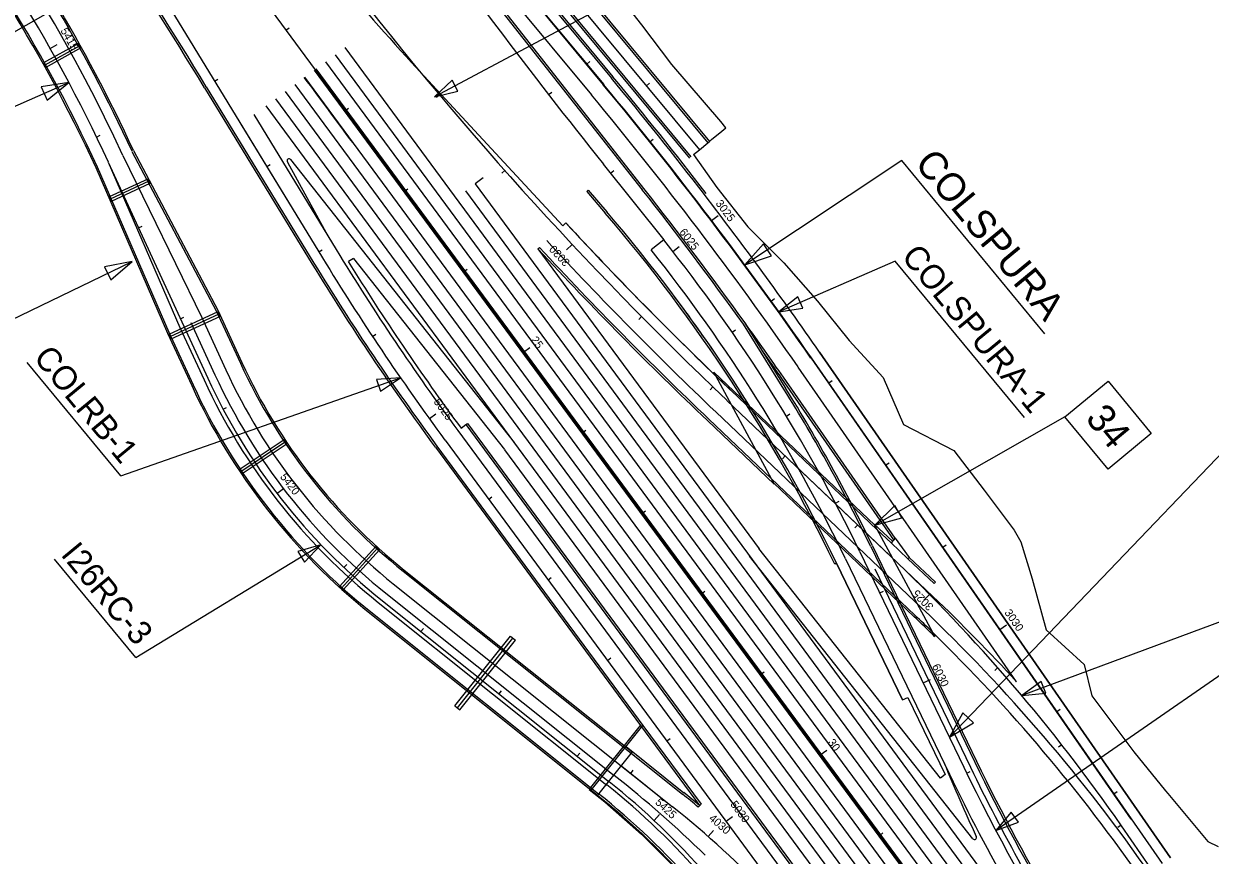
# Model space of a CAD drawing. Extents: x 1944333 to 1975203, y 788957 to 827579.
# Drawn here: x 1970195 to 1971381, y 796150 to 796981 of the extents above; entities that cross this region are included whole.
import ezdxf

# ---------------------------------------------------------------- set-up
doc = ezdxf.new("R2010")
doc.units = 0
for name, color, linetype in [('BR_CENTER LINES', 7, 'Continuous'), ('BR_CONCRETE', 7, 'Continuous'), ('RD_HC_CL_Rel', 7, 'Continuous'), ('RD_HC_Data_Tic_Rel', 7, 'Continuous'), ('RD_HC_TX_Rel_Sta50', 7, 'Continuous'), ('RD_PD_ALT1_LnLine', 7, 'Continuous'), ('RD_PD_ALT1_TrvlWay', 7, 'Continuous'), ('RD_PD_ALT3_LnLine', 7, 'Continuous'), ('RD_PD_CstnLmt', 7, 'Continuous'), ('RD_PD_GR', 7, 'Continuous'), ('RD_PD_MedBWall', 7, 'Continuous'), ('RD_PD_PaveShd', 7, 'Continuous'), ('RD_PD_WallFill', 7, 'Continuous'), ('RD_QTY_Conc4Structures', 7, 'Continuous'), ('RD_TX_RoadID', 7, 'Continuous')]:
    doc.layers.add(name, color=color, linetype=linetype)

msp = doc.modelspace()

# ---------------------------------------------------------------- linework, layer by layer
at = {"layer": 'BR_CENTER LINES'}
for p, q in [((1970250.9, 796958.7), (1970215.9, 796939.3)), ((1970320, 796823.3), (1970281.3, 796805.5)), ((1970390.1, 796690.4), (1970341, 796667.8)), ((1970456.7, 796562.8), (1970411.8, 796532.8)), ((1970548.6, 796456.5), (1970512.4, 796416.4)), ((1970628.3, 796297.1), (1970683.8, 796366.6))]:
    msp.add_line(p, q, dxfattribs=at)
at = {"layer": 'BR_CONCRETE'}
for p, q in [((1970249.7, 796960.9), (1970214.7, 796941.5)), ((1970252.1, 796956.5), (1970217.1, 796937.1)), ((1970252.1, 796956.5), (1970249.7, 796960.9)), ((1970214.7, 796941.5), (1970217.1, 796937.1)), ((1970303.1, 796853.2), (1970387.4, 796693.9)), ((1970304.6, 796854), (1970388.9, 796694.6)), ((1970267, 796837), (1970338.6, 796671.6)), ((1970268.5, 796837.6), (1970340.1, 796672.3)), ((1970318.9, 796825.5), (1970280.2, 796807.7)), ((1970321, 796821), (1970318.9, 796825.5)), ((1970321, 796821), (1970282.3, 796803.2)), ((1970280.2, 796807.7), (1970282.3, 796803.2)), ((1970387.4, 796693.9), (1970411.5, 796641.4)), ((1970388.9, 796694.6), (1970413, 796642.1)), ((1970389.1, 796692.7), (1970340, 796670.1)), ((1970391.2, 796688.1), (1970342.1, 796665.6)), ((1970391.2, 796688.1), (1970389.1, 796692.7)), ((1970338.6, 796671.6), (1970362.8, 796619)), ((1970340, 796670.1), (1970342.1, 796665.6)), ((1970340.1, 796672.3), (1970364.3, 796619.7)), ((1970944.4, 796521.6), (1970884.6, 796632.6)), ((1971045.5, 796479.6), (1970884.6, 796632.6)), ((1971047.9, 796475), (1970887.1, 796628)), ((1970455.3, 796564.9), (1970410.4, 796534.9)), ((1970458.1, 796560.7), (1970455.3, 796564.9)), ((1970458.1, 796560.7), (1970413.2, 796530.7)), ((1970410.4, 796534.9), (1970413.2, 796530.7)), ((1971085.6, 796389.5), (1970941.9, 796526.2)), ((1971084.5, 796388.3), (1970944.4, 796521.6)), ((1971105.6, 796367.9), (1971045.5, 796479.6)), ((1970546.7, 796458.2), (1970510.6, 796418.1)), ((1970550.5, 796454.9), (1970546.7, 796458.2)), ((1970550.5, 796454.9), (1970514.3, 796414.8)), ((1970574.3, 796433.4), (1970801.9, 796251.7)), ((1970575.3, 796434.7), (1970802.9, 796252.9)), ((1970510.6, 796418.1), (1970514.3, 796414.8)), ((1970540.8, 796391.5), (1970768.4, 796209.8)), ((1970541.8, 796392.8), (1970769.4, 796211)), ((1970625.7, 796299.1), (1970681.3, 796368.7)), ((1970630.8, 796295.1), (1970686.3, 796364.6)), ((1970681.3, 796368.7), (1970686.3, 796364.6)), ((1970625.7, 796299.1), (1970630.8, 796295.1)), ((1970802.9, 796252.9), (1970768.4, 796209.8))]:
    msp.add_line(p, q, dxfattribs=at)
for centre, radius, start, end in [((1968885.8, 796201.6), 1520.4, 24.6902, 54.7761), ((1968885.8, 796201.6), 1522, 24.6902, 54.7761), ((1968885.8, 796201.6), 1560, 24.6902, 49.7691), ((1968885.8, 796201.6), 1561.6, 24.6902, 49.7691), ((1970931.2, 796880.4), 572, 204.6902, 231.3903), ((1970931.2, 796880.4), 570.4, 204.6902, 231.3903), ((1970931.2, 796880.4), 625.6, 204.6902, 231.3903), ((1970931.2, 796880.4), 624, 204.6902, 231.3903), ((1969897.2, 795140.5), 1722.4, 45.4469, 46.4244), ((1969897.2, 795140.5), 1724, 45.6209, 46.4244)]:
    msp.add_arc(centre, radius, start, end, dxfattribs=at)
at = {"layer": 'RD_HC_CL_Rel'}
for p, q in [((1970371.4, 797456.1), (1970870.2, 796854.8)), ((1970391.3, 797381.2), (1970774.1, 796919.7)), ((1970235.6, 797274.6), (1971221.4, 795937.4)), ((1970226.8, 797183.8), (1970493.6, 796746.7)), ((1970279.5, 796842.4), (1970378.8, 796626.4)), ((1970774.1, 796840.5), (1970834.5, 796764.7)), ((1970981.7, 796646.5), (1971301.4, 796185.7)), ((1971060.5, 796449.2), (1970897.5, 796604.3)), ((1970616, 796564.6), (1971026.4, 796007.8)), ((1971030.6, 796452.9), (1971134.5, 796237.5)), ((1970551.8, 796405.3), (1970780.1, 796223)), ((1970792.6, 796238.6), (1970843.3, 796198.1)), ((1971378.8, 796053.9), (1971291.9, 796179.1))]:
    msp.add_line(p, q, dxfattribs=at)
for centre, radius, start, end in [((1969482, 796626.9), 1166, 35.6021, 163.611), ((1968885.8, 796201.6), 1534, 24.6902, 54.7761), ((1976020.6, 801023.6), 6710, 215.60211, 218.56681), ((1973505.9, 799345.7), 3784, 217.5434, 226.4244), ((1967695.8, 794366.3), 3999.5, 34.7587, 39.6755), ((1969544.4, 795736), 1650, 25.75, 38.5668), ((1972641.1, 798057.5), 2516, 211.3977, 216.3977), ((1970931.2, 796880.4), 608, 204.6902, 231.3903), ((1969854.2, 795181.4), 1750, 34.7587, 46.4244), ((1972899.9, 797089), 1960, 205.75, 218.6115), ((1970309.6, 795633.8), 754, 30.7638, 51.3903), ((1970211.8, 795407.3), 1012, 36.3977, 51.3903)]:
    msp.add_arc(centre, radius, start, end, dxfattribs=at)
at = {"layer": 'RD_HC_Data_Tic_Rel'}
for p, q in [((1970456.9, 796974.4), (1970460.1, 796976.8)), ((1970221.4, 796956.1), (1970228.4, 796960)), ((1970757.7, 796940.3), (1970760.7, 796942.9)), ((1970385.7, 796923.4), (1970389.1, 796925.5)), ((1970817.2, 796918.7), (1970820.3, 796921.2)), ((1970610.3, 796909.6), (1970607.3, 796907)), ((1970719.5, 796910), (1970722.6, 796912.4)), ((1970516.2, 796894), (1970519.5, 796896.3)), ((1970267.7, 796867.5), (1970271.3, 796869.2)), ((1970821, 796862.9), (1970824.1, 796865.4)), ((1970437.8, 796838), (1970441.2, 796840.1)), ((1970675.7, 796834), (1970672.7, 796831.3)), ((1970781.3, 796831.4), (1970784.5, 796833.9)), ((1970575.6, 796813.5), (1970578.8, 796815.8)), ((1970882.4, 796784), (1970888.8, 796788.9)), ((1970309.7, 796776.7), (1970313.3, 796778.4)), ((1970489.9, 796752.7), (1970493.3, 796754.8)), ((1970743.1, 796760.1), (1970737.2, 796754.6)), ((1970843.6, 796753.2), (1970849.9, 796758.1)), ((1970634.9, 796733), (1970638.1, 796735.3)), ((1970941.9, 796703.6), (1970945.1, 796706)), ((1970351.5, 796685.9), (1970355.1, 796687.5)), ((1970812.4, 796688), (1970809.5, 796685.1)), ((1970543.5, 796668.2), (1970546.8, 796670.5)), ((1970902.9, 796672.6), (1970906.2, 796674.9)), ((1970694.3, 796652.5), (1970700.7, 796657.2)), ((1970999.4, 796621.8), (1971002.7, 796624.1)), ((1970883.5, 796617.7), (1970880.8, 796614.8)), ((1970394.1, 796595.4), (1970397.7, 796597.3)), ((1970600.3, 796586), (1970606.8, 796590.7)), ((1970957.1, 796588.6), (1970960.5, 796590.7)), ((1970753.6, 796572), (1970756.8, 796574.4)), ((1970955.9, 796548.7), (1970953.2, 796545.8)), ((1971056.4, 796539.7), (1971059.7, 796541.9)), ((1970448, 796511.3), (1970454.4, 796516.2)), ((1970659.6, 796505.4), (1970662.8, 796507.8)), ((1971006.1, 796501.5), (1971009.7, 796503.4)), ((1970812.9, 796491.5), (1970816.2, 796493.9)), ((1971028.4, 796479.8), (1971025.6, 796476.9)), ((1971113.4, 796457.5), (1971116.7, 796459.8)), ((1970515, 796437.2), (1970517.7, 796440.1)), ((1970718.9, 796424.9), (1970722.1, 796427.3)), ((1970872.3, 796411), (1970875.5, 796413.4)), ((1971050.4, 796411.8), (1971054, 796413.6)), ((1971100.2, 796410.2), (1971094.5, 796404.6)), ((1970591.9, 796373.3), (1970594.4, 796376.4)), ((1971170.4, 796375.3), (1971177, 796379.9)), ((1970778.2, 796344.4), (1970781.5, 796346.8)), ((1970931.6, 796330.5), (1970934.8, 796332.9)), ((1971168.4, 796337.1), (1971165.4, 796334.4)), ((1970670, 796310.9), (1970672.5, 796314)), ((1971093.8, 796321.8), (1971101, 796325.2)), ((1971227.4, 796293.2), (1971230.7, 796295.5)), ((1970837.6, 796263.9), (1970840.8, 796266.3)), ((1970991, 796250), (1970997.4, 796254.8)), ((1971232.2, 796260.1), (1971229.1, 796257.7)), ((1970748.1, 796248.5), (1970750.6, 796251.6)), ((1970801.6, 796231.4), (1970804.1, 796234.5)), ((1971137.3, 796231.7), (1971140.9, 796233.4)), ((1971284.4, 796211), (1971287.7, 796213.3)), ((1970824.8, 796184.3), (1970830.3, 796190.2)), ((1970896.9, 796183.5), (1970903.4, 796188.2)), ((1970879, 796168.2), (1970884.3, 796174.2)), ((1971050.3, 796169.5), (1971053.5, 796171.9)), ((1971291.6, 796179.7), (1971288.3, 796177.4))]:
    msp.add_line(p, q, dxfattribs=at)
at = {"layer": 'RD_PD_ALT1_LnLine'}
for p, q in [((1970515.8, 796956.9), (1971235.5, 795980.7)), ((1970506.2, 796949.8), (1971226.1, 795973.2)), ((1970465.9, 796920.1), (1971186.9, 795942.1)), ((1970456.3, 796913), (1971177.5, 795934.6)), ((1970446.6, 796905.8), (1971168.1, 795927.1)), ((1970636.3, 796813.6), (1971204.2, 796043.4)), ((1970362, 796682.2), (1970386.1, 796629.7)), ((1970556.8, 796411.5), (1970785.1, 796229.2))]:
    msp.add_line(p, q, dxfattribs=at)
for centre, radius, start, end in [((1970931.2, 796880.4), 600, 204.6902, 231.3903), ((1970125.7, 795385.7), 1070.7, 45.5181, 51.9846)]:
    msp.add_arc(centre, radius, start, end, dxfattribs=at)
at = {"layer": 'RD_PD_ALT1_TrvlWay'}
for p, q in [((1970379.9, 797463.1), (1970878.6, 796861.8)), ((1970363, 797449.1), (1970861.7, 796847.8)), ((1970616.6, 797110.3), (1970774.5, 796920)), ((1970604.3, 797100.1), (1970762.2, 796909.8)), ((1970496.5, 796942.6), (1971216.7, 795965.8)), ((1970475.6, 796927.2), (1971196.3, 795949.6)), ((1970436.9, 796898.7), (1971158.7, 795919.6)), ((1970424.9, 796889.9), (1970507.2, 796755.1)), ((1970412, 796880.3), (1970493.6, 796746.7)), ((1970294.1, 796849.1), (1970372.9, 796687.2)), ((1970279.5, 796842.4), (1970351.1, 796677.2)), ((1970458.5, 796842.5), (1970497.1, 796771.6)), ((1970461.7, 796844.9), (1970685, 796562.2)), ((1970646, 796820.8), (1971250.6, 796000.6)), ((1970834.5, 796764.7), (1970822, 796754.7)), ((1970372.9, 796687.2), (1970397, 796634.7)), ((1970351.1, 796677.2), (1970375.2, 796624.7)), ((1971332.8, 796141.4), (1970982.1, 796646.7)), ((1971187.2, 796323.1), (1970968.9, 796637.6)), ((1971103.5, 796408.3), (1970897.5, 796604.3)), ((1970886.5, 796592.7), (1971092.5, 796396.7)), ((1970616, 796564.6), (1971026.4, 796007.8)), ((1970628.8, 796574), (1971128.6, 795896.1)), ((1971143.5, 796166.1), (1970920.3, 796448.7)), ((1971016.2, 796445.9), (1971120.1, 796230.5)), ((1970564.3, 796420.9), (1970843.3, 796198.1)), ((1970549.3, 796402.1), (1970777.6, 796219.8))]:
    msp.add_line(p, q, dxfattribs=at)
for centre, radius, start, end in [((1968885.8, 796201.6), 1534, 24.6902, 54.7761), ((1968885.8, 796201.6), 1550, 24.6902, 49.7691), ((1967695.8, 794366.3), 4000, 34.7587, 39.6755), ((1967695.8, 794366.3), 3984, 34.7587, 39.6755), ((1970460.1, 796843.7), 2, 36.3977, 216.3977), ((1972641.1, 798057.5), 2500, 211.3977, 216.3977), ((1973505.9, 799345.7), 3800, 222.7981, 226.4244), ((1969544.4, 795736), 1634, 25.75, 38.5668), ((1972641.1, 798057.5), 2516, 211.3977, 216.3977), ((1970931.2, 796880.4), 588, 204.6902, 231.3903), ((1970931.2, 796880.4), 612, 204.6902, 231.3903), ((1969897.2, 795140.5), 1734, 34.7587, 46.4244), ((1969897.2, 795140.5), 1750, 42.5124, 46.4244), ((1972945.2, 796997.9), 1980.5, 202.444, 204.759), ((1970309.6, 795633.8), 750, 30.7638, 51.3903), ((1972899.9, 797089), 1976, 205.75, 213.4208), ((1970211.8, 795407.3), 1012, 36.3977, 51.3903), ((1971145.1, 796167.3), 2, 216.3977, 36.3977)]:
    msp.add_arc(centre, radius, start, end, dxfattribs=at)
at = {"layer": 'RD_PD_ALT3_LnLine'}
msp.add_arc((1961247.8, 790023.8), 11524, 36.39766, 36.80076, dxfattribs=at)
at = {"layer": 'RD_PD_CstnLmt'}
for p, q in [((1971338.2, 796211.2), (1971378.2, 796163.3)), ((1971378.2, 796163.3), (1971388.6, 796158.4))]:
    msp.add_line(p, q, dxfattribs=at)
for points in [[(1970864.4, 796850), (1970870.2, 796854.8), (1970878.6, 796861.8), (1970880.2, 796863.1), (1970882.3, 796864.9), (1970892.5, 796873.3), (1970896.6, 796876.7), (1970891.7, 796883.1), (1970875.4, 796902), (1970842.7, 796939.9), (1970812.6, 796979.8), (1970781.8, 797019.3)], [(1970864.4, 796850), (1970887.5, 796817.2), (1970918.6, 796777.7), (1970954.7, 796741.7), (1970988.1, 796703.5), (1971019.7, 796664.1), (1971053.9, 796627), (1971074.1, 796580.2), (1971124.4, 796554.2), (1971154.7, 796514.4), (1971184.8, 796474.4), (1971191.5, 796463), (1971202.8, 796426), (1971216.6, 796374.8), (1971254.6, 796340.3), (1971262.4, 796308.9), (1971274.2, 796293.1), (1971304.3, 796253), (1971335.9, 796214.1), (1971338.2, 796211.2)], [(1970760, 796215.3), (1970775.5, 796202.9), (1970812.2, 796170.8), (1970812.2, 796170.8), (1970812.3, 796170.7), (1970846.6, 796136.3)]]:
    msp.add_lwpolyline(points, dxfattribs=at)
at = {"layer": 'RD_PD_GR'}
for p, q in [((1970990.3, 796652.4), (1971340.9, 796147.1)), ((1971079.9, 796447.3), (1971078.6, 796445.9)), ((1971104.7, 796421.1), (1971078.6, 796445.9)), ((1971106, 796422.5), (1971079.9, 796447.3)), ((1971073.2, 796304.8), (1971007.2, 796441.6)), ((1971106, 796422.5), (1971104.7, 796421.1))]:
    msp.add_line(p, q, dxfattribs=at)
for centre, radius, start, end in [((1967695.8, 794366.3), 4010, 34.7587, 37.546), ((1973505.9, 799345.7), 3774, 222.7981, 226.0583), ((1969897.2, 795140.5), 1724, 34.7587, 45.6209)]:
    msp.add_arc(centre, radius, start, end, dxfattribs=at)
at = {"layer": 'RD_PD_MedBWall'}
for p, q in [((1970485.2, 796934.3), (1971205.4, 795957.4)), ((1970486.9, 796935.5), (1971207, 795958.7)), ((1971064.4, 796464.9), (1970952.5, 796626.2)), ((1971065.9, 796466.4), (1970954.1, 796627.4)), ((1970811.2, 796279.4), (1970870.3, 796199.3)), ((1970813.8, 796279.4), (1970871.9, 796200.5)), ((1970780.8, 796268.5), (1970853.3, 796210.6)), ((1970796.9, 796258.2), (1970854.6, 796212.1)), ((1970871.9, 796200.5), (1970869, 796197.8))]:
    msp.add_line(p, q, dxfattribs=at)
for centre, radius, start, end in [((1967695.8, 794366.3), 3966, 34.7587, 35.7176), ((1967695.8, 794366.3), 3964, 34.7587, 35.2497), ((1970211.8, 795407.3), 1028, 50.2601, 51.3903), ((1970211.8, 795407.3), 1030, 50.2601, 51.3903)]:
    msp.add_arc(centre, radius, start, end, dxfattribs=at)
at = {"layer": 'RD_PD_PaveShd'}
for p, q in [((1970381.4, 797464.4), (1970880.2, 796863.1)), ((1970361.4, 797447.8), (1970860.2, 796846.5)), ((1970733.8, 796778.9), (1970582.6, 796942.1)), ((1970654, 796826.7), (1970646, 796820.8)), ((1970733.8, 796778.9), (1970736.7, 796781.6)), ((1970708.8, 796755.8), (1970929.8, 796456)), ((1970524.5, 796746.1), (1970519.4, 796743)), ((1970524.5, 796746.1), (1970675.3, 796555.1)), ((1971341, 796147.1), (1970990.3, 796652.4)), ((1970632.1, 796576.4), (1970636.9, 796580)), ((1970675.5, 796554.9), (1971149.3, 795912.2)), ((1971111, 796226.6), (1970929.7, 796456.2)), ((1971007.2, 796441.6), (1971073.2, 796304.8)), ((1971045.4, 796436), (1971141.1, 796237.6)), ((1971073.2, 796304.8), (1971078.6, 796307.4)), ((1971078.6, 796307.4), (1971115.7, 796230.3)), ((1971115.7, 796230.3), (1971111, 796226.6))]:
    msp.add_line(p, q, dxfattribs=at)
for centre, radius, start, end in [((1972045.7, 798296.9), 1994, 219.0581, 222.7981), ((1967695.8, 794366.3), 4010, 34.7587, 37.546), ((1973505.9, 799345.7), 3774, 222.7981, 226.4244), ((1972641.1, 798057.5), 2496, 211.7801, 216.3977), ((1972901, 797086.5), 1954, 205.75, 212.2292)]:
    msp.add_arc(centre, radius, start, end, dxfattribs=at)
at = {"layer": 'RD_PD_WallFill'}
for p, q in [((1970399.4, 797387.9), (1970782.2, 796926.4)), ((1970400.9, 797389.2), (1970783.8, 796927.7)), ((1970813.2, 796814.8), (1970595.1, 797092.5)), ((1970814.7, 796816.1), (1970596.6, 797093.7)), ((1970375.7, 796916.8), (1970483.3, 796740.5)), ((1970377.4, 796917.8), (1970485, 796741.5)), ((1970759.1, 796814.3), (1970757.6, 796813)), ((1970757.6, 796813), (1970776.1, 796791.4)), ((1970759.1, 796814.3), (1970777.6, 796792.7)), ((1970708.8, 796755.8), (1970710.3, 796757.1)), ((1970956.4, 796616.6), (1970915.8, 796681.6)), ((1970954.7, 796615.5), (1970914.1, 796680.5)), ((1970636.9, 796580), (1970638.5, 796581.2)), ((1970636.9, 796580), (1971149.6, 795884.4)), ((1970638.5, 796581.2), (1971151.3, 795885.6)), ((1970878.2, 796584), (1970944.9, 796520.6)), ((1970879.6, 796585.5), (1970941.9, 796526.2)), ((1970606.3, 796557.4), (1970811.2, 796279.4)), ((1970607.9, 796558.6), (1970813.8, 796279.4)), ((1971047.9, 796475), (1971044.9, 796480.7)), ((1971044.9, 796480.7), (1971063, 796463.4)), ((1971047.9, 796475), (1971061.7, 796462)), ((1971041.4, 796458.1), (1971145.3, 796242.7)), ((1971043.2, 796458.9), (1971147.1, 796243.5)), ((1971079.9, 796447.3), (1971078.6, 796445.9)), ((1971007.2, 796441.6), (1971005.4, 796440.7)), ((1970760.3, 796215.6), (1970811.2, 796279.4)), ((1970761.9, 796214.5), (1970813.8, 796279.4))]:
    msp.add_line(p, q, dxfattribs=at)
for centre, radius, start, end in [((1963181.8, 792526), 8428, 31.39766, 33.97915), ((1963181.8, 792526), 8430, 31.39766, 33.97947), ((1967695.8, 794366.3), 4010, 37.546, 39.6755), ((1967695.8, 794366.3), 4012, 37.546, 39.6755), ((1967695.8, 794366.3), 3964, 35.7195, 38.1487), ((1967695.8, 794366.3), 3966, 35.7176, 38.1486), ((1969544.4, 795736), 1622, 25.75, 40.5931), ((1969544.4, 795736), 1624, 25.75, 40.5931), ((1973505.9, 799345.7), 3812, 222.7981, 226.4244), ((1973505.9, 799345.7), 3810, 222.7981, 226.4244), ((1972641.1, 798057.5), 2528, 211.3977, 216.3977), ((1972641.1, 798057.5), 2526, 211.3977, 216.3977), ((1969544.4, 795736), 1624, 34.472, 36.8306), ((1969544.4, 795736), 1662, 25.75, 31.949), ((1969544.4, 795736), 1664, 25.75, 31.949), ((1972899.9, 797089), 1948, 205.75, 216.0047), ((1972899.9, 797089), 1946, 205.75, 215.9432), ((1970309.6, 795633.8), 736, 30.7638, 52.2411), ((1970309.6, 795633.8), 738, 30.7638, 51.4626)]:
    msp.add_arc(centre, radius, start, end, dxfattribs=at)
at = {"layer": 'RD_QTY_Conc4Structures'}
for p, q in [((1971065.9, 796466.4), (1971061.7, 796462)), ((1971061.7, 796462), (1971078.6, 796445.9)), ((1971065.9, 796466.4), (1971079.9, 796447.3)), ((1971078.6, 796445.9), (1971079.9, 796447.3))]:
    msp.add_line(p, q, dxfattribs=at)
at = {"layer": 'RD_TX_RoadID'}
for p, q in [((1971215.5, 796670.9), (1971072.4, 796844.2)), ((1971194.9, 796587), (1971065.8, 796743.3)), ((1970292, 796528.9), (1970198.5, 796642.1)), ((1970306.9, 796347.3), (1970225.8, 796445.4))]:
    msp.add_line(p, q, dxfattribs=at)
for points in [[(1970074.5, 796909.4), (1970442.4, 797119.5)], [(1970818, 797021.4), (1970605.5, 796907.8)], [(1969972.8, 796804.4), (1970240.1, 796921.9)], [(1971072.4, 796844.2), (1970915.6, 796739.7)], [(1970080.6, 796635.4), (1970303.3, 796743.1)], [(1971065.8, 796743.3), (1970949.7, 796692.7)], [(1971554.2, 796720.6), (1971120, 796267.5)], [(1970292, 796528.9), (1970571.4, 796626.9)], [(1971235.3, 796587.7), (1971045.5, 796479.6)], [(1970306.9, 796347.3), (1970492, 796459.9)], [(1971539.8, 796433), (1971166.3, 796174.4)], [(1971473.3, 796413.4), (1971192.3, 796309.3)]]:
    msp.add_lwpolyline(points, dxfattribs=at)
for points in [[(1970218.3, 796904.4), (1970240.1, 796921.9), (1970212.5, 796917.7)], [(1970623, 796924.3), (1970605.5, 796907.8), (1970628.9, 796913.3)], [(1970934.1, 796760.7), (1970915.6, 796739.7), (1970942.1, 796748.6)], [(1970282.1, 796724.8), (1970303.3, 796743.1), (1970275.8, 796737.9)], [(1970968.5, 796707.7), (1970949.7, 796692.7), (1970973.4, 796696.3)], [(1970551.6, 796613.4), (1970571.4, 796626.9), (1970547.5, 796625.1)], [(1971278.5, 796623.4), (1971321.6, 796571.1), (1971278.5, 796535.4), (1971235.3, 796587.7)], [(1971065.4, 796499.3), (1971045.5, 796479.6), (1971072.6, 796486.7)], [(1970475.5, 796442.6), (1970492, 796459.9), (1970469, 796453.2)], [(1971211.8, 796323.2), (1971192.3, 796309.3), (1971216.2, 796311.6)], [(1971133.5, 796292), (1971120, 796267.5), (1971144, 796282)], [(1971181.8, 796192.7), (1971166.3, 796174.4), (1971188.9, 796182.5)]]:
    msp.add_lwpolyline(points, close=True, dxfattribs=at)

# ---------------------------------------------------------------- texts
at = {"layer": 'RD_HC_TX_Rel_Sta50'}
for s, rotation, p in [('5415', 299.4606, (1970231.4, 796973.9)), ('3025', 307.1888, (1970885.9, 796801)), ('6025', 308.0577, (1970849.6, 796772.3)), ('3030', 133.1029, (1970741.4, 796742.8)), ('25', 306.3977, (1970701.4, 796664.7)), ('5025', 305.7933, (1970604.2, 796602.8)), ('5420', 307.3703, (1970450.7, 796527.7)), ('3025', 134.6019, (1971104.7, 796398.8)), ('3030', 304.7587, (1971174.6, 796392.1)), ('6030', 295.75, (1971102.4, 796338.6)), ('30', 306.3977, (1970998.1, 796262.3)), ('5425', 316.902, (1970825.4, 796201.6)), ('5030', 306.3977, (1970900.6, 796200.4)), ('4030', 318.7536, (1970879, 796185.5))]:
    msp.add_text(s, height=8, rotation=rotation, dxfattribs=at).set_placement(p)
at = {"layer": 'RD_TX_RoadID'}
for s, height, p in [(' COLSPURA', 28, (1971077.8, 796848.7)), ('COLSPURA-1', 24, (1971071.2, 796747.7)), ('COLRB-1 ', 24, (1970203.9, 796646.6)), ('34', 28, (1971255, 796585.8)), ('I26RC-3 ', 24, (1970231.2, 796449.9))]:
    msp.add_text(s, height=height, rotation=309.5517, dxfattribs=at).set_placement(p)

doc.saveas('drawing.dxf')
